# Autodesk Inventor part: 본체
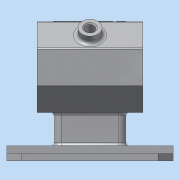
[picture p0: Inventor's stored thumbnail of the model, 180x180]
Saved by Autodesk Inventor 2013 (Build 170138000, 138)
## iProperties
Created: 2018-06
Part Number: 본체
Material: 알루미늄 6061
Document SubType Name: Modeling
Designer: Administrator
Density: 2.71 g/cm^3
Mass: 554.043 g
Surface Area: 601.935 cm^2
Volume: 204.444 cm^3
Author: Administrator
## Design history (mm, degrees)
sketch "스케치1" dims "d18" = 60
  geometry: L1 (0, 30)-(-12.426, 30); L2 (0, 30)-(12.426, 30); L3 (-12.426, 30)-(-30, 12.426); L4 (12.426, 30)-(30, 12.426); L5 (-30, 12.426)-(-30, -12.426); L6 (-30, -12.426)-(-12.426, -30); L7 (-12.426, -30)-(12.426, -30); L8 (30, 12.426)-(30, -12.426); L9 (12.426, -30)-(30, -12.426); 1 further point
  constraints: 18 end point, 4 perpendicular, 2 equal length, 2 horizontal, 1 vertical alignment, 2 other
extrude "돌출1" new body sketch "스케치1" distance "d14" = 35; taper "d16" = 0 deg; dims "d15" = 35, "d17" = 0
sketch "스케치2"
  geometry: C1 r 16 at (0, 0); 1 further point
  constraints: 1 centre point, 1 coincident
  dimensions: "d20" = 32 diameter of C1
extrude "돌출2" cut sketch "스케치2" distance "d21" = 12; taper "d22" = 0 deg
sketch "스케치4"
  geometry: C1 r 16 at (0, 0); 1 further point
  constraints: 1 centre point, 1 coincident
  dimensions: "d26" = 32 diameter of C1
extrude "돌출4" cut sketch "스케치4" distance "d27" = 12; taper "d28" = 0 deg
sketch "스케치5"
  geometry: C1 r 16 at (0, 0) reference; C2 r 14 at (0, 0)
  constraints: 1 centre point, 1 coincident
  dimensions: "d29" = 28 diameter of C2
extrude "돌출5" cut sketch "스케치5" distance "d30" = 3; taper "d31" = 0 deg
sketch "스케치6"
  geometry: C1 r 16 at (0, 0) reference; C2 r 14 at (0, 0)
  constraints: 1 centre point, 1 coincident
  dimensions: "d32" = 28 diameter of C2
extrude "돌출6" cut sketch "스케치6" distance "d33" = 3; taper "d34" = 0 deg
sketch "스케치7"
  geometry: L1 (-14, 20)-(14, 20) reference; L2 (14, -20)-(-14, -20) reference; L3 (0, 20)-(25, 20); L4 (25, 20)-(25, -20); L5 (25, -20)-(0, -20); L6 (0, 20)-(0, -20); 1 further point
  constraints: 8 end point, 2 midpoint, 1 perpendicular, 1 point on line
  dimensions: "d35" = 25 distance of L3.start L3.end; "d36" = 40 distance of L3.end L4.end
revolve "회전1" sketch "스케치7" stored, may be unused: angle "d37" = 90 deg
node "작업 평면1"
sketch "스케치8"
  geometry: L1 (45, -55)-(-45, -55); L2 (-55, -45)-(-55, 45); L3 (-45, 55)-(45, 55); L4 (55, 45)-(55, -45); L5 (55, -55)-(-55, 55); L6 (-55, -55)-(55, 55); L7 (55, -45)-(45, -55); L8 (55, 45)-(45, 55); L9 (-45, 55)-(-55, 45); L10 (-45, -55)-(-55, -45); 1 further point
  constraints: 20 end point, 8 point on line, 2 midpoint, 2 parallel, 1 horizontal, 1 perpendicular
  dimensions: "d39" = 110 distance of L5.end L6.end; "d40" = 110 distance of L6.start L5.end; "d41" = 10 distance of L4.end L5.start; "d42" = 10 distance of L1.start L5.start (= d41); "d43" = 10 distance of L4.start L6.end (= d41); "d44" = 10 distance of L3.end L6.end (= d43); "d45" = 10 distance of L3.start L5.end (= d41); "d46" = 10 distance of L2.end L5.end (= d45); "d47" = 10 distance of L1.end L6.start (= d41); "d48" = 10 distance of L2.start L6.start (= d47)
extrude "돌출7" join sketch "스케치8" distance "d49" = 5; taper "d50" = 0 deg
sketch "스케치9"
  geometry: L1 (-25, 55)-(25, 55); L2 (25, 55)-(25, -55); L3 (25, -55)-(-25, -55); L4 (-25, -55)-(-25, 55); L5 (-25, 55)-(25, -55); L6 (25, 55)-(-25, -55); 1 further point
  constraints: 12 end point, 2 midpoint, 2 parallel, 1 horizontal, 1 perpendicular
  dimensions: "d51" = 50 distance of L2.end L3.end; "d52" = 110 distance of L1.end L2.end
extrude "돌출8" join sketch "스케치9" distance "d53" = 5; taper "d54" = 0 deg
sketch "스케치10"
  geometry: L1 (-55, 45)-(-55, -45) reference; L2 (5, -19)-(5, 19); L3 (-5, 19)-(-5, -19); A1 r 5 centre (0, -19) between (-5, -19) and (5, -19); A2 r 5 centre (0, 19) between (5, 19) and (-5, 19); 1 further point
  constraints: 4 end point, 4 point on circle, 2 centre point, 1 parallel
extrude "돌출9" join sketch "스케치10" stored distance "d59" = 5; taper "d60" = 0 deg
fillet "모깎기1" dims "d61" = 3
fillet "모깎기2" dims "d62" = 0.3
chamfer "모따기1" distance "d63" = 1; stored, may be unused: second distance "d64" = 2, angle "d65" = 45 deg
fillet "모깎기3" dims "d66" = 2
sketch "스케치11"
  geometry: C1 r 17 at (0, 0) reference; A1 r 23 centre (0, 0) between (0, 23) and (-23, 0); 2 further points
  constraints: 4 point on circle, 1 centre point, 1 coincident
  dimensions: "d67" = 46 diameter of A1
hole "구멍1" sketch "스케치11" at (0, 23), (-23, 0), (0, -23), (23, 0) diameter "d68" = 3.242; stored, may be unused: countersink angle "d72" = 90 deg, drill point angle "d74" = 118 deg; dims "d69" = 8, "d70" = 4, "d71" = 2, "d73" = 10
sketch "스케치12"
  geometry: L1 (0, 0)-(0, 37.698); L2 (0, 0)-(21.213, 21.213); L3 (30, 12.426)-(12.426, 30) reference
  constraints: 4 end point, 1 midpoint, 1 vertical
  dimensions: "d76" = 45 deg angle of L1 L2
node "작업 평면2"
sketch "스케치13"
  geometry: C1 r 8 at (0, 0); 1 further point
  constraints: 1 centre point, 1 coincident
  dimensions: "d77" = 16 diameter of C1
extrude "돌출10" join sketch "스케치13" distance "d78" = 7; taper "d79" = 0 deg
sketch "스케치14"
  geometry: C1 r 8 at (0, 0) reference; C2 r 4 at (0, 0)
  constraints: 1 centre point, 1 coincident
  dimensions: "d80" = 8 diameter of C2
extrude "돌출11" cut sketch "스케치14" stored distance "d81" = 7; taper "d82" = 0 deg
chamfer "모따기2" distance "d83" = 1; stored, may be unused: second distance "d84" = 2, angle "d85" = 45 deg
fillet "모깎기4" dims "d86" = 1
fillet "모깎기5" dims "d87" = 3
sketch "스케치15"
  geometry: C1 r 5 at (45, 0); 1 further point
  constraints: 1 centre point
  dimensions: "d89" = 10 diameter of C1
extrude "돌출12" cut sketch "스케치15" stored distance "d90" = 7; taper "d91" = 0 deg
node "작업 평면3"
sketch "스케치16"
  geometry: L1 (-12.012, 35)-(12.012, 35) reference; L2 (30, -35)-(30, 35) reference; 2 further points
  constraints: 1 coincident, 1 other
  dimensions: "d95" = 35 distance from line of L1 point (0, 0) (derived); "d96" = 30 distance from line of L2 point (0, 0) (derived)
feature "엠보싱1" sketch "스케치16" dims "d18" = 60, "d93" = 0.5, "d94" = 0
node "솔리드1"
mirror "대칭1"
mirror "대칭2"
other parameters: "d38" = -62, "d92" = 64.75
